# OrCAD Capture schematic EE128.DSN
size A
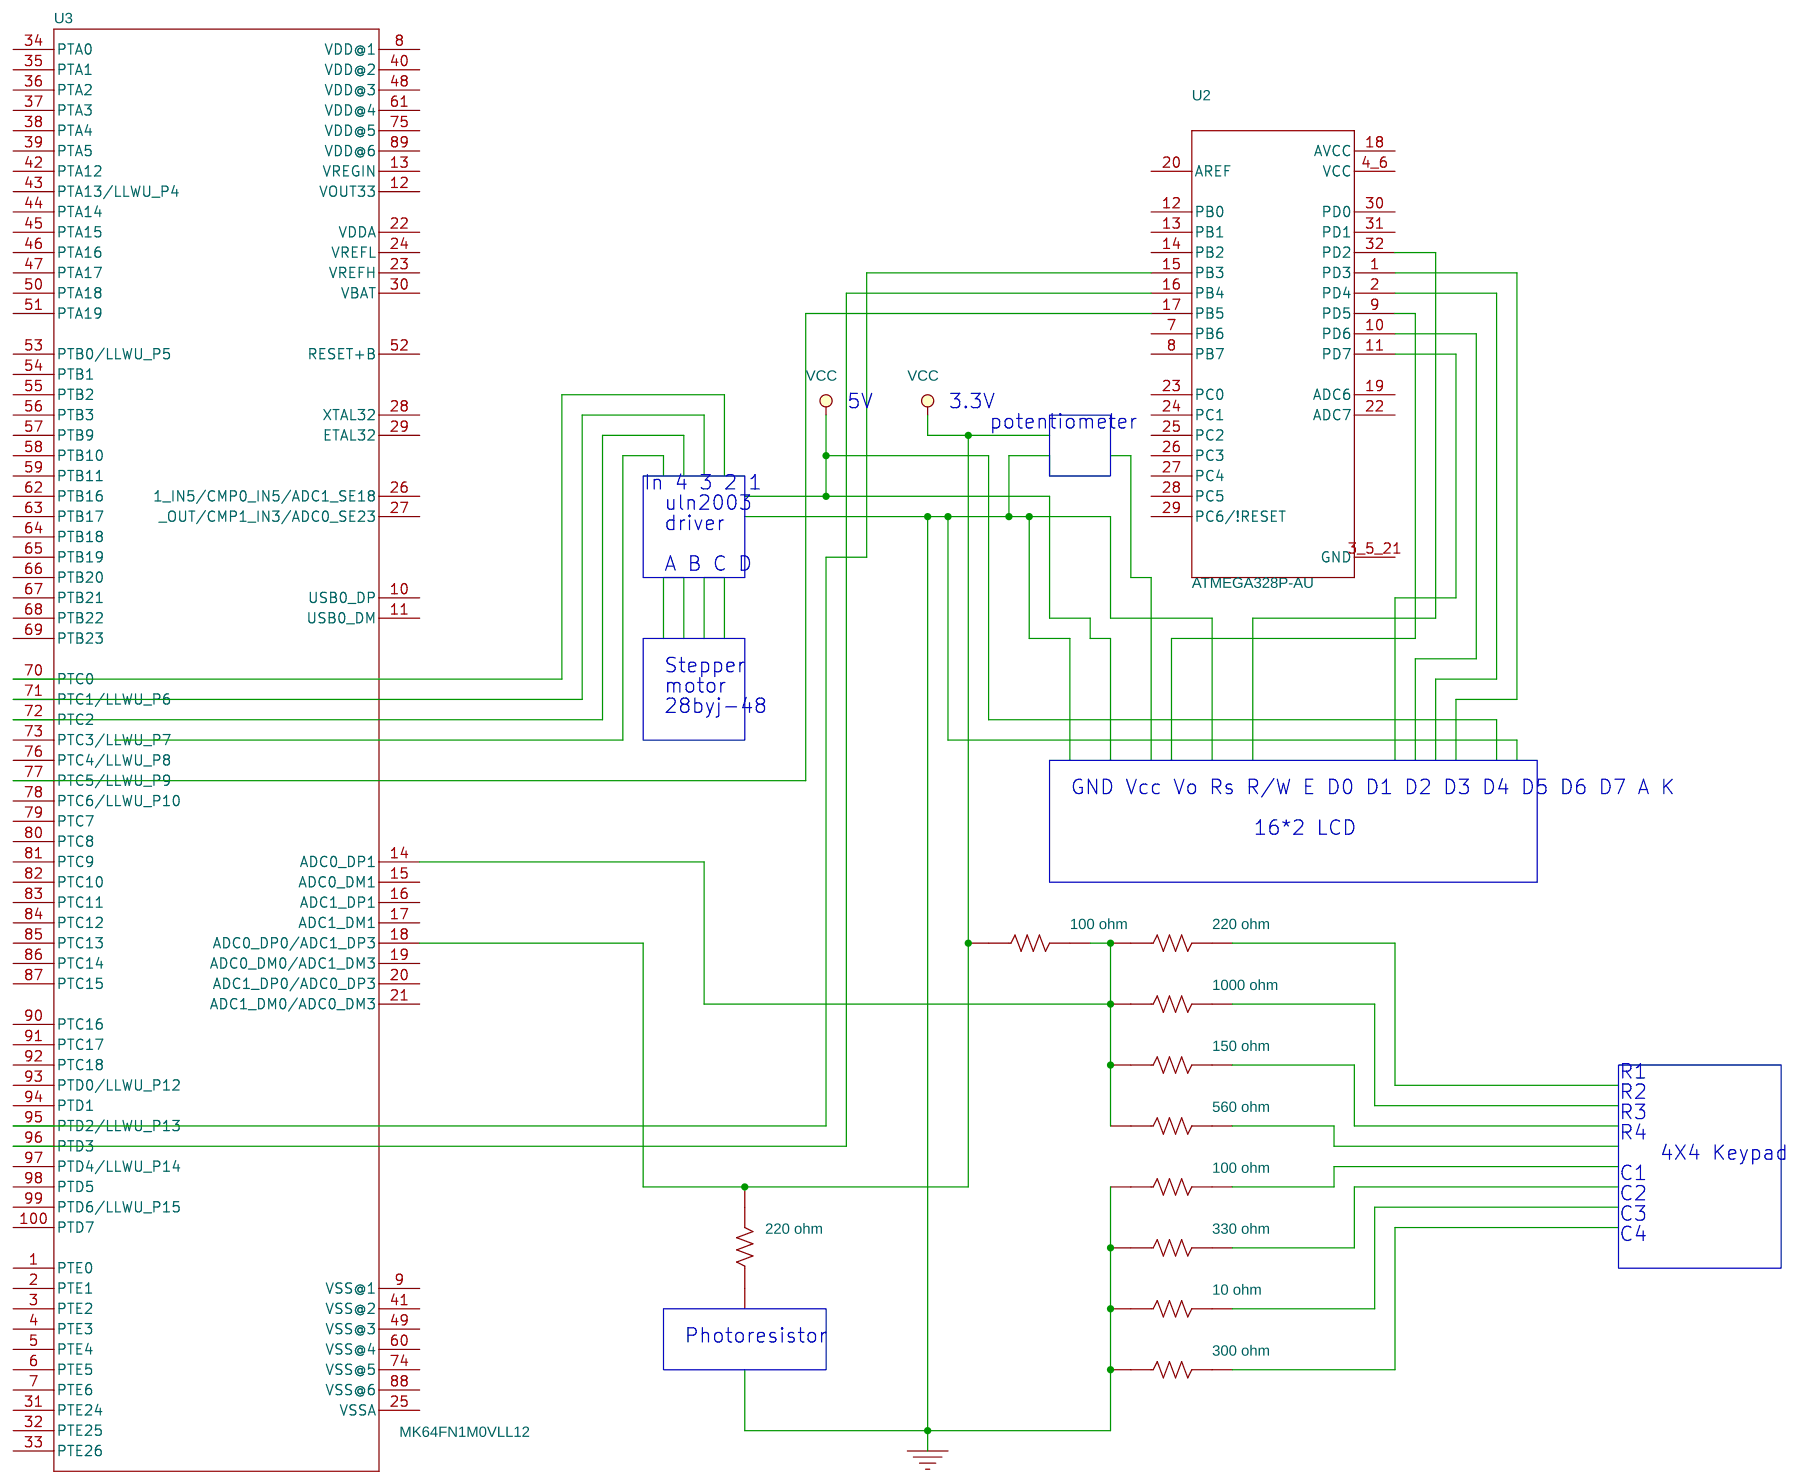
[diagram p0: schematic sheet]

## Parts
10 ohm  Resistor  [P1G]
100 ohm  Resistor  [P1G]
100 ohm#2  Resistor  [P1G]
150 ohm  Resistor  [P1G]
220 ohm  Resistor  [P1G]
220 ohm#2  Resistor  [P1G]
300 ohm  Resistor  [P1G]
330 ohm  Resistor  [P1G]
560 ohm  Resistor  [P1G]
1000 ohm  Resistor  [P1G]
U2  ATMEGA328P-AU
U3  MK64FN1M0VLL12  [QFP50P1600X1600X170-100N]

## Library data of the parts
10 ohm 100 ohm 100 ohm#2 150 ohm 220 ohm 220 ohm#2 300 ohm 330 ohm 560 ohm 1000 ohm = Resistor_0
U2 = ATMEGA328P-AU
U3 = MK64FN1M0VLL12

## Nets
GND: 10 ohm.1 100 ohm.1 300 ohm.1 330 ohm.1
VBAT: U3.30(VBAT)
VCC: 100 ohm#2.1 220 ohm#2.2 U3.18(ADC0_DP0/ADC1_DP3)
VDD@1: U3.8(VDD@1)
VDD@2: U3.40(VDD@2)
VDD@3: U3.48(VDD@3)
VDD@4: U3.61(VDD@4)
VDD@5: U3.75(VDD@5)
VDD@6: U3.89(VDD@6)
VDDA: U3.22(VDDA)
VSS@1: U3.9(VSS@1)
VSS@2: U3.41(VSS@2)
VSS@3: U3.49(VSS@3)
VSS@4: U3.60(VSS@4)
VSS@5: U3.74(VSS@5)
VSS@6: U3.88(VSS@6)
VSSA: U3.25(VSSA)
VOUT33: U3.12(VOUT33)
VREFH: U3.23(VREFH)
VREFL: U3.24(VREFL)
VREGIN: U3.13(VREGIN)
N10831: U2.15(PB3) U3.95(PTD2/LLWU_P13)
N10835: U2.16(PB4) U3.96(PTD3)
N10839: U2.17(PB5) U3.77(PTC5/LLWU_P9)
N13473: 100 ohm#2.2 150 ohm.1 220 ohm.1 560 ohm.1 1000 ohm.1 U3.14(ADC0_DP1)

Not connected (* = marked no-connect by the designer): 10 ohm 2; 100 ohm 2; 150 ohm 2; 220 ohm 2; 220 ohm#2 1; 300 ohm 2; 330 ohm 2; 560 ohm 2; 1000 ohm 2; U2 1(PD3) 2(PD4) 3 5 21(GND) 4 6(VCC) 7(PB6) 8(PB7) 9(PD5) 10(PD6) 11(PD7) 12(PB0) 13(PB1) 14(PB2) 18(AVCC) 19(ADC6) 20(AREF) 22(ADC7) 23(PC0) 24(PC1) 25(PC2) 26(PC3) 27(PC4) 28(PC5) 29(PC6/!RESET) 30(PD0) 31(PD1) 32(PD2); U3 1(PTE0) 2(PTE1) 3(PTE2) 4(PTE3) 5(PTE4) 6(PTE5) 7(PTE6) 10(USB0_DP) 11(USB0_DM) 15(ADC0_DM1) 16(ADC1_DP1) 17(ADC1_DM1) 19(ADC0_DM0/ADC1_DM3) 20(ADC1_DP0/ADC0_DP3) 21(ADC1_DM0/ADC0_DM3) 26(1_IN5/CMP0_IN5/ADC1_SE18) 27(_OUT/CMP1_IN3/ADC0_SE23) 28(XTAL32) 29(ETAL32) 31(PTE24) 32(PTE25) 33(PTE26) 34(PTA0) 35(PTA1) 36(PTA2) 37(PTA3) 38(PTA4) 39(PTA5) 42(PTA12) 43(PTA13/LLWU_P4) 44(PTA14) 45(PTA15) 46(PTA16) 47(PTA17) 50(PTA18) 51(PTA19) 52(RESET+B) 53(PTB0/LLWU_P5) 54(PTB1) 55(PTB2) 56(PTB3) 57(PTB9) 58(PTB10) 59(PTB11) 62(PTB16) 63(PTB17) 64(PTB18) 65(PTB19) 66(PTB20) 67(PTB21) 68(PTB22) 69(PTB23) 70(PTC0) 71(PTC1/LLWU_P6) 72(PTC2) 73(PTC3/LLWU_P7) 76(PTC4/LLWU_P8) 78(PTC6/LLWU_P10) 79(PTC7) 80(PTC8) 81(PTC9) 82(PTC10) 83(PTC11) 84(PTC12) 85(PTC13) 86(PTC14) 87(PTC15) 90(PTC16) 91(PTC17) 92(PTC18) 93(PTD0/LLWU_P12) 94(PTD1) 97(PTD4/LLWU_P14) 98(PTD5) 99(PTD6/LLWU_P15) 100(PTD7)

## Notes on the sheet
- 5V
- 3.3V
- potentiometer
- In 4 3 2 1
- uln2003
- driver
- A B C D
- Stepper
- motor
- 28byj-48
- GND Vcc Vo Rs R/W E D0 D1 D2 D3 D4 D5 D6 D7 A K
- 16*2 LCD
- R1
- R2
- R3
- R4
- 4X4 Keypad
- C1
- C2
- C3
- C4
- Photoresistor
